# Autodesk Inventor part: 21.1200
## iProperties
Created: 2006-02
Part Number: 21.1200
Material: Steel, Mild
Description: M8 x 16 SHCS
Document SubType Name: Modeling
Standard: DIN 7984
Designer: Andy Moles
Standards Organization: DIN
Language: en-US
Size Designation: M8 x 16
Categories: <MemberInstance><Categories><Category DisplayName="Fasteners" InternalName="e4da775c-781d-43d5-af7c-5136215cf5a6" Mnemonic="FSTN"><Category DisplayName="Bolts"
Density: 7.86 g/cm^3
Mass: 10.6827 g
Surface Area: 9.17139 cm^2
Volume: 1.35912 cm^3
Vendor: S
Author: Andy Moles
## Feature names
1. Body [Revolution]
2. Slot [Extrusion]
3. Fillet1
4. Chamfer1
